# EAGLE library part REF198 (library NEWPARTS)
Precision Micropower, Low Dropout Voltage References
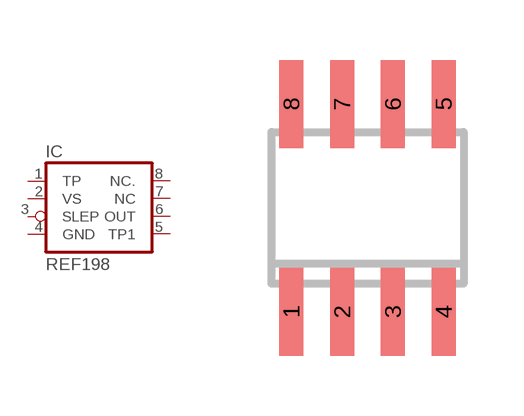
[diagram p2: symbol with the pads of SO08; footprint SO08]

Designator prefix IC

## REF198D  [SO08]
1  TP  in
2  VS  in
3  SLEP  in
4  GND  pwr
5  TP1  pwr
6  OUT  in
7  NC  in
8  NC.  out

## Footprint SO08 (pad centres in mm)
Small Outline Package 8 NS Package M08A
smd 0.6 x 2.2: 1 -1.905,-2.6; 2 -0.635,-2.6; 3 0.635,-2.6; 4 1.905,-2.6; 5 1.905,2.6; 6 0.635,2.6; 7 -0.635,2.6; 8 -1.905,2.6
